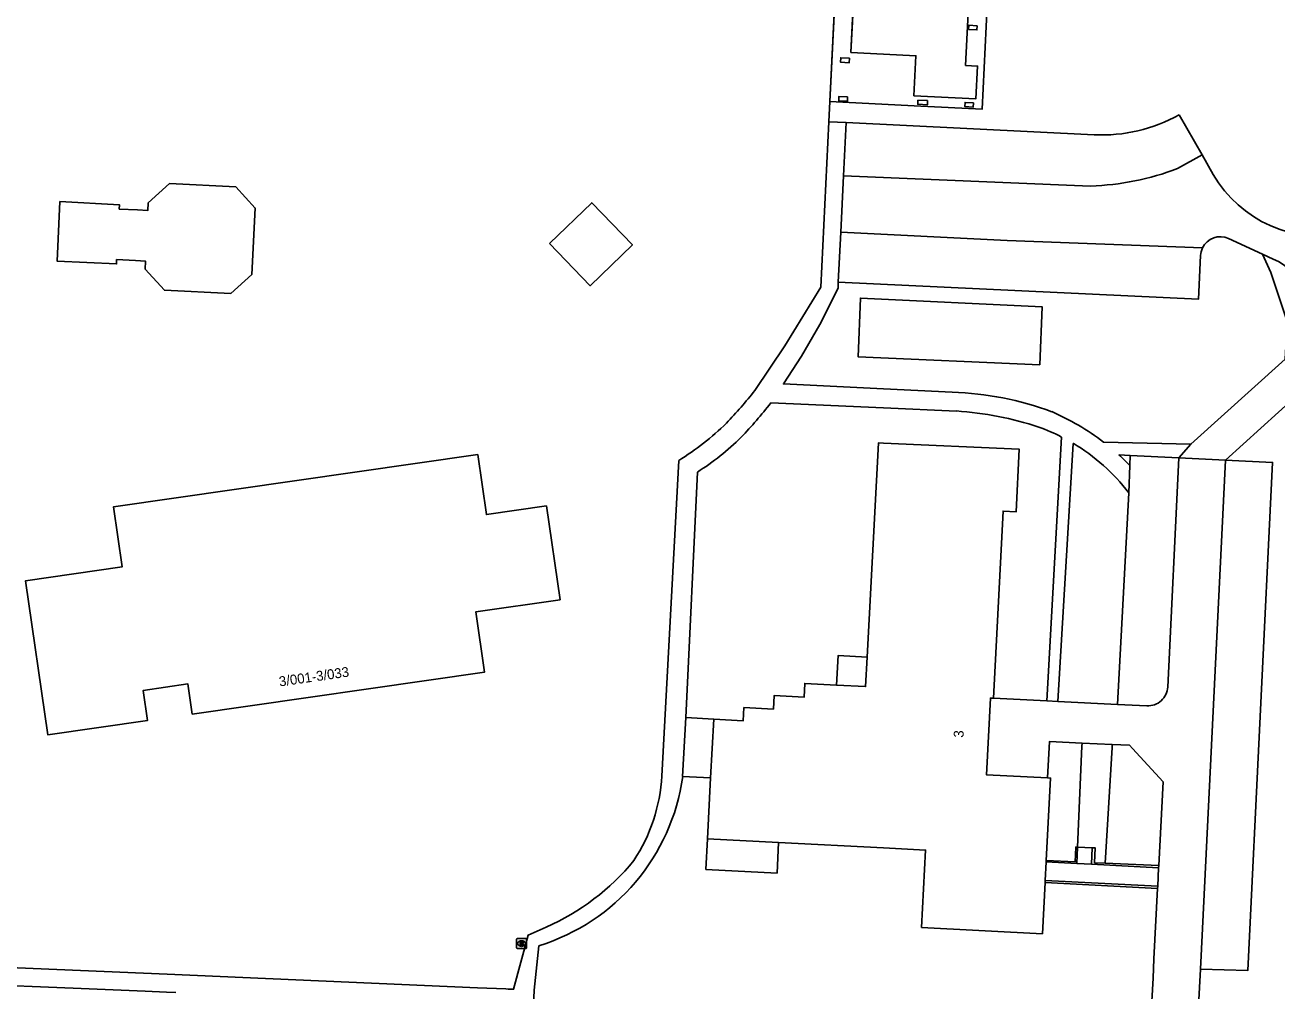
# Model space of a CAD drawing. Extents: x 161761 to 162722, y 384793 to 385405.
# Drawn here: x 161913.2 to 162039.8, y 385152.1 to 385249.7 of the extents above; entities that cross this region are included whole.
import ezdxf

# ---------------------------------------------------------------- set-up
doc = ezdxf.new("R2010")
doc.units = 0
for name, color, linetype in [('IMGEO_Brandkraan', 7, 'Continuous'), ('IMGEO_Erf', 7, 'Continuous'), ('IMGEO_Muur', 7, 'Continuous'), ('IMGEO_Pand', 7, 'Continuous'), ('IMGEO_Pand_nummerreeks', 7, 'Continuous'), ('IMGEO_Pand_overbouw', 7, 'Continuous'), ('IMGEO_Parkeervlak_open', 7, 'Continuous'), ('IMGEO_Rijbaan_lokaal_open', 7, 'Continuous'), ('IMGEO_Voetpad_open', 7, 'Continuous')]:
    doc.layers.add(name, color=color, linetype=linetype)

msp = doc.modelspace()

# ---------------------------------------------------------------- linework, layer by layer
at = {"layer": 'IMGEO_Brandkraan'}
for p, q in [((161962.91, 385156.44), (161962.91, 385157.29)), ((161962.99, 385157.36), (161963.84, 385157.36)), ((161963.4, 385157.14), (161963.42, 385157.14)), ((161963.91, 385157.29), (161963.91, 385156.44)), ((161963.84, 385156.36), (161962.99, 385156.36)), ((161963.42, 385156.58), (161963.4, 385156.58))]:
    msp.add_line(p, q, dxfattribs=at)
for points in [[(161962.91, 385156.44), (161962.91, 385157.29)], [(161962.99, 385157.36), (161963.84, 385157.36)], [(161963.26, 385157.06), (161963.26, 385156.66), (161963.47, 385156.66)], [(161963.49, 385157.06), (161963.26, 385157.06)], [(161963.44, 385156.98), (161963.38, 385156.98), (161963.38, 385156.91)], [(161963.38, 385156.91), (161963.44, 385156.91)], [(161963.45, 385156.83), (161963.38, 385156.83), (161963.38, 385156.75)], [(161963.38, 385156.75), (161963.45, 385156.75)], [(161963.91, 385157.29), (161963.91, 385156.44)], [(161963.84, 385156.36), (161962.99, 385156.36)]]:
    msp.add_lwpolyline(points, dxfattribs=at)
for centre, radius, start, end in [((161962.99, 385157.29), 0.0765, 91.552, 178.448), ((161962.99, 385157.29), 0.0765, 91.552, 178.448), ((161963.44, 385156.94), 0.0379, 267.8285, 90.9355), ((161963.45, 385156.79), 0.0404, 269.8759, 90.5077), ((161963.48, 385156.91), 0.251, 268.6676, 293.5347), ((161963.49, 385156.92), 0.145, 59.4692, 91.5367), ((161963.52, 385156.96), 0.0922, 285.5137, 58.1501), ((161963.52, 385156.77), 0.105, 301.3115, 78.989), ((161963.84, 385157.29), 0.0765, 1.552, 88.448), ((161963.84, 385157.29), 0.0765, 1.552, 88.448), ((161962.99, 385156.44), 0.0765, 181.552, 268.448), ((161962.99, 385156.44), 0.0765, 181.552, 268.448), ((161963.84, 385156.44), 0.0765, 271.552, 358.448), ((161963.84, 385156.44), 0.0765, 271.552, 358.448)]:
    msp.add_arc(centre, radius, start, end, dxfattribs=at)
for centre, major_axis, ratio, start_param, end_param in [((161963.4, 385156.86), (-0.387, 0.002), 0.722429, 4.712389, 7.853982), ((161963.42, 385156.86), (-0.39, 0.002), 0.717154, 1.570796, 4.712389)]:
    msp.add_ellipse(centre, major_axis=major_axis, ratio=ratio, start_param=start_param, end_param=end_param, dxfattribs=at)
at = {"layer": 'IMGEO_Erf'}
msp.add_lwpolyline([(161994.48, 385239.89), (161994.58, 385241.94), (161994.97, 385250), (161996.33, 385278.06), (161996.34, 385278.13)], dxfattribs=at)
at = {"layer": 'IMGEO_Muur'}
for points in [[(162019.59, 385166.6), (162019.42, 385166.61), (162019.35, 385165.11), (162016.43, 385165.24)], [(162019.59, 385166.6), (162019.52, 385164.95)], [(162021.02, 385164.87), (162021.09, 385166.54)], [(162022.38, 385164.97), (162021.32, 385165.02), (162021.39, 385166.53), (162021.09, 385166.54)], [(162019.52, 385164.95), (162016.43, 385165.11)], [(162027.79, 385164.53), (162021.02, 385164.87)], [(162027.8, 385164.74), (162022.38, 385164.97)], [(162027.8, 385164.74), (162027.79, 385164.53)], [(162016.32, 385163.03), (162027.69, 385162.43)], [(162016.33, 385163.24), (162027.7, 385162.65)], [(162027.7, 385162.65), (162027.69, 385162.43)]]:
    msp.add_lwpolyline(points, dxfattribs=at)
at = {"layer": 'IMGEO_Pand'}
for points in [[(162013.07, 385257.77), (162010.78, 385257.89), (162008.91, 385257.98), (162008.52, 385250.18), (162008.29, 385245.58), (162009.5, 385245.52), (162009.33, 385242.21), (162003.07, 385242.52), (162003.27, 385246.56), (162000, 385246.72), (161996.7, 385246.89), (161996.86, 385250), (161998.23, 385277.95), (161998.39, 385280.86), (161999.09, 385295.28), (161997.18, 385295.37)], [(162009.46, 385249.59), (162009.43, 385249.17), (162008.58, 385249.21), (162008.61, 385249.64), (162009.46, 385249.59)], [(161996.55, 385246.31), (161996.53, 385245.85), (161995.65, 385245.9), (161995.67, 385246.35), (161996.55, 385246.31)], [(161996.36, 385242.41), (161996.34, 385241.96), (161995.46, 385242), (161995.48, 385242.45), (161996.36, 385242.41)], [(162004.45, 385242.03), (162004.43, 385241.6), (162003.45, 385241.65), (162003.47, 385242.07), (162004.45, 385242.03)], [(162009.07, 385241.81), (162009.05, 385241.38), (162008.22, 385241.42), (162008.24, 385241.85), (162009.07, 385241.81)], [(161934.02, 385222.54), (161927.31, 385222.87), (161925.37, 385225.01), (161925.39, 385225.82), (161924.38, 385225.87), (161922.49, 385225.96), (161922.48, 385225.52), (161916.47, 385225.81), (161916.76, 385231.82), (161922.77, 385231.51), (161922.75, 385231.07), (161924.61, 385230.98), (161925.65, 385230.94), (161925.68, 385231.71), (161927.84, 385233.65), (161934.55, 385233.31), (161936.49, 385231.17), (161936.16, 385224.47), (161934.02, 385222.54)], [(161966.23, 385227.58), (161970.51, 385231.7), (161974.61, 385227.44), (161970.33, 385223.32), (161966.23, 385227.58)], [(162011.09, 385181.64), (162012.08, 385200.55), (162013.41, 385200.48), (162013.69, 385206.82), (162000, 385207.43), (161999.48, 385207.45), (161998.34, 385185.8)], [(161958.98, 385206.27), (161959.86, 385200.2), (161965.93, 385201.07), (161967.3, 385191.59), (161958.8, 385190.38), (161959.67, 385184.29), (161930.13, 385180.05), (161929.69, 385183.09), (161925.18, 385182.43), (161925.61, 385179.4), (161915.53, 385177.96), (161913.28, 385193.51), (161923.04, 385194.91), (161922.16, 385200.98), (161958.98, 385206.27)], [(161995.24, 385182.97), (161998.18, 385182.82), (161998.34, 385185.8)], [(161995.24, 385182.97), (161992.03, 385183.14), (161991.96, 385181.75), (161988.93, 385181.91), (161988.86, 385180.55), (161985.88, 385180.71), (161985.81, 385179.38), (161982.83, 385179.54)], [(162011.09, 385181.64), (162010.8, 385181.66), (162010.39, 385173.92), (162016.56, 385173.59)], [(161982.52, 385173.59), (161982.83, 385179.54)], [(161982.52, 385173.59), (161982.2, 385167.45)], [(162016.56, 385173.59), (162016.87, 385173.58), (162016.43, 385165.24)], [(161989.39, 385167.07), (161982.2, 385167.45)], [(161989.39, 385167.07), (162000, 385166.52), (162004.24, 385166.3), (162003.83, 385158.5), (162016.05, 385157.86), (162016.32, 385163.03)], [(162016.43, 385165.11), (162016.33, 385163.24)], [(162016.43, 385165.24), (162016.43, 385165.11)], [(162016.33, 385163.24), (162016.32, 385163.03)]]:
    msp.add_lwpolyline(points, dxfattribs=at)
at = {"layer": 'IMGEO_Pand_overbouw'}
for points in [[(161996.7, 385246.89), (161999.09, 385295.28), (161997.18, 385295.37), (161994.58, 385241.94), (162003.1, 385241.51), (162009.95, 385241.16), (162010.78, 385257.89), (162008.91, 385257.98), (162008.52, 385250.18), (162008.29, 385245.58), (162009.5, 385245.52), (162009.33, 385242.21), (162003.07, 385242.52), (162003.27, 385246.56)], [(161995.24, 385182.97), (161998.18, 385182.82), (161998.34, 385185.8), (161995.39, 385185.95)], [(161982.83, 385179.54), (161980, 385179.69), (161979.69, 385173.74), (161982.52, 385173.59)], [(161989.39, 385167.07), (161982.2, 385167.45), (161982.04, 385164.35), (161989.23, 385163.98)]]:
    msp.add_lwpolyline(points, close=True, dxfattribs=at)
at = {"layer": 'IMGEO_Parkeervlak_open'}
for points in [[(162029.86, 385240.58), (162032.18, 385236.54)], [(161996.2, 385239.8), (162021.28, 385238.58)], [(162032.03, 385226.37), (162031.81, 385221.96), (161995.42, 385223.67)], [(162024.89, 385205.17), (162024.92, 385206.18)], [(162032.02, 385154.29), (162036.81, 385154.15), (162039.31, 385205.47), (162034.55, 385205.7)], [(162024.79, 385202.4), (162023.62, 385181.03)]]:
    msp.add_lwpolyline(points, dxfattribs=at)
for centre, radius, start, end in [((162022.06, 385254.63), 16.07, 267.2007, 299.0331), ((162034.05, 385226.26), 2.02, 154.131, 177.0709)]:
    msp.add_arc(centre, radius, start, end, dxfattribs=at)
at = {"layer": 'IMGEO_Rijbaan_lokaal_open'}
for points in [[(162032.18, 385236.54), (162029.71, 385235.16)], [(162032.18, 385236.54), (162033.31, 385234.57)], [(161995.66, 385228.72), (161995.94, 385234.41)], [(162020.92, 385233.39), (161995.94, 385234.41)], [(162032.23, 385227.15), (162012.49, 385227.9), (161995.66, 385228.72)], [(162038.29, 385226.51), (162034.86, 385228.09)], [(162038.29, 385226.51), (162039.38, 385226.01)], [(162029.85, 385205.93), (162028.71, 385182.78)], [(162034.55, 385205.7), (162029.85, 385205.93)], [(162032.02, 385154.29), (162034.55, 385205.7)], [(162016.49, 385181.38), (162011.09, 385181.64)], [(162016.49, 385181.38), (162017.59, 385181.32)], [(162023.62, 385181.03), (162017.59, 385181.32)], [(162026.61, 385180.88), (162023.62, 385181.03)], [(162016.56, 385173.59), (162016.76, 385177.27), (162020.05, 385177.12)], [(162020.05, 385177.12), (162023.11, 385176.99)], [(162023.11, 385176.99), (162024.84, 385176.92), (162025.16, 385176.57), (162028.24, 385173.2), (162027.8, 385164.74)], [(162027.79, 385164.53), (162027.7, 385162.65)], [(162027.69, 385162.43), (162027.32, 385155.33), (162027.23, 385153.37), (162026.66, 385143.46)], [(162030.52, 385127.16), (162030.75, 385130.88), (162032.02, 385154.29)]]:
    msp.add_lwpolyline(points, dxfattribs=at)
for centre, radius, start, end in [((162020.03, 385260.55), 27.17, 271.8635, 290.8566), ((162044.19, 385240.89), 12.58, 210.1487, 281.8576), ((162034.03, 385226.27), 2, 65.3426, 153.9899), ((162036.2, 385219.17), 7.55, 357.386, 65.0628), ((162026.71, 385182.88), 2, 267.1404, 357.2135)]:
    msp.add_arc(centre, radius, start, end, dxfattribs=at)
at = {"layer": 'IMGEO_Voetpad_open'}
for points in [[(161986.98, 385212.75), (161990.02, 385217.24), (161993.66, 385223.17), (161994.48, 385239.89)], [(161996.2, 385239.8), (161994.48, 385239.89)], [(161995.94, 385234.41), (161996.2, 385239.8)], [(161995.66, 385228.72), (161995.42, 385223.67)], [(162031.04, 385207.3), (162040.59, 385215.92), (162040.78, 385219.71), (162039.13, 385224.67), (162038.29, 385226.51)], [(161995.42, 385223.67), (161995.39, 385223.09), (161993.57, 385219.42), (161991.69, 385216.2), (161989.87, 385213.4), (162000, 385212.9), (162006.94, 385212.56)], [(162015.78, 385215.32), (161997.42, 385216.14), (161997.66, 385222.07), (162016.03, 385221.19), (162015.78, 385215.32)], [(162034.55, 385205.7), (162043.48, 385213.78)], [(161988.6, 385211.49), (162000, 385210.99), (162007.35, 385210.66)], [(162017.99, 385208.04), (162016.49, 385181.38)], [(162017.59, 385181.32), (162019.15, 385207.4)], [(162022.22, 385207.53), (162031.04, 385207.3)], [(162029.85, 385205.93), (162031.04, 385207.3)], [(162023.78, 385206.23), (162024.92, 385206.18)], [(162024.92, 385206.18), (162029.85, 385205.93)], [(161977.59, 385173.79), (161979.29, 385205.66)], [(162024.79, 385202.4), (162024.89, 385205.17)], [(161980, 385179.69), (161981.18, 385204.49)], [(161998.34, 385185.8), (161995.39, 385185.95), (161995.24, 385182.97)], [(161979.69, 385173.74), (161980, 385179.69)], [(161982.83, 385179.54), (161980, 385179.69)], [(162019.59, 385166.6), (162020.04, 385176.79), (162020.05, 385177.12)], [(162023.11, 385176.99), (162023.09, 385176.66), (162022.38, 385164.97)], [(161979.69, 385173.74), (161982.52, 385173.59)], [(161982.2, 385167.45), (161982.04, 385164.35), (161989.23, 385163.98), (161989.39, 385167.07)], [(162021.09, 385166.54), (162019.59, 385166.6)], [(162019.52, 385164.95), (162021.02, 385164.87)], [(161901.23, 385154.93), (161902.89, 385157.22), (161908.26, 385155.48), (161908.37, 385158.54), (161910.26, 385158.5), (161910.05, 385154.51), (161927.58, 385153.78), (161958.97, 385152.4), (161961.82, 385152.28), (161962.06, 385152.27), (161962.61, 385152.24), (161964.07, 385157.72), (161965.89, 385158.53)], [(161967.88, 385129.39), (161965.45, 385129.52), (161964.36, 385134.39), (161963.95, 385134.41), (161964.69, 385152.15), (161965.16, 385156.64)], [(161908.14, 385152.77), (161918.08, 385152.35), (161925.36, 385152.04), (161927.52, 385151.95), (161928.47, 385151.91)]]:
    msp.add_lwpolyline(points, dxfattribs=at)
for centre, radius, start, end in [((161953, 385239.24), 43.09, 316.225, 322.0594), ((162006.08, 385181.47), 31.1, 69.4775, 88.4165), ((161953.08, 385239.16), 45.03, 316.2341, 322.0816), ((162005.14, 385177.12), 33.62, 71.7297, 86.233), ((162007.09, 385187.73), 24.92, 52.6237, 66.6023), ((161964.64, 385229.39), 27.88, 301.6987, 314.3122), ((162008.93, 385190.22), 19.99, 63.0543, 70.2735), ((161967.52, 385226.13), 25.59, 302.2532, 314.9367), ((162008.94, 385190.23), 19.98, 37.5275, 59.2711), ((162007.3, 385187.96), 24.61, 44.3667, 47.9501), ((161959.03, 385176.58), 20.86, 287.1133, 352.1695), ((161960.36, 385174.77), 17.26, 326.5777, 356.746), ((161956.25, 385180.46), 23.96, 293.7191, 320.6111)]:
    msp.add_arc(centre, radius, start, end, dxfattribs=at)

# ---------------------------------------------------------------- texts
at = {"layer": 'IMGEO_Pand_nummerreeks'}
for s, rotation, p in [('3/001-3/033', 8.1818, (161938.97, 385182.83)), ('3', 87.0036, (162008.07, 385177.64))]:
    msp.add_text(s, height=1, rotation=rotation, dxfattribs=at).set_placement(p)

doc.saveas('drawing.dxf')
